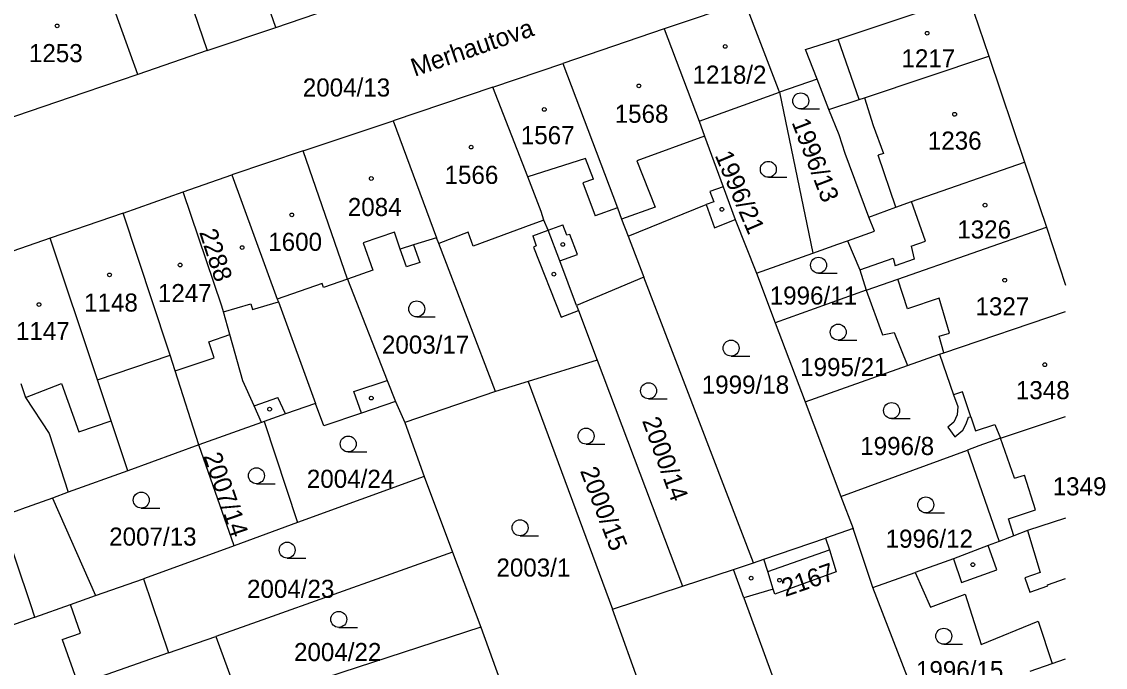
# Model space of a CAD drawing. Extents: x -564952 to -564307, y -1202373 to -1201847.
# Drawn here: x -564412.8 to -564310.9, y -1202215.7 to -1202155 of the extents above; entities that cross this region are included whole.
import ezdxf

# ---------------------------------------------------------------- set-up
doc = ezdxf.new("R2010")
doc.units = 0
for name, color, linetype in [('Hranice parcel', 7, 'Continuous'), ('Parcelní čísla', 7, 'Continuous'), ('Pop  PČ popisy', 7, 'Continuous'), ('Vnitřní kresba', 7, 'Continuous'), ('Značky budov', 7, 'Continuous'), ('Značky kultur', 7, 'Continuous')]:
    doc.layers.add(name, color=color, linetype=linetype)

msp = doc.modelspace()

# ---------------------------------------------------------------- linework, layer by layer
at = {"layer": 'Hranice parcel'}
for p, q in [((-564323.81, -1202152.55), (-564321.87, -1202158.24)), ((-564388.94, -1202155.54), (-564382.59, -1202153.39)), ((-564344.81, -1202153.14), (-564352.41, -1202155.68)), ((-564395.37, -1202157.69), (-564388.94, -1202155.54)), ((-564352.41, -1202155.68), (-564361.94, -1202158.92)), ((-564352.41, -1202155.68), (-564349.13, -1202164.34)), ((-564395.37, -1202157.69), (-564401.92, -1202159.96)), ((-564368.52, -1202161.14), (-564361.94, -1202158.92)), ((-564321.87, -1202158.24), (-564318.53, -1202168.2)), ((-564338.02, -1202160.39), (-564341.55, -1202161.62)), ((-564336.91, -1202163.24), (-564338.02, -1202160.39)), ((-564368.52, -1202161.14), (-564377.89, -1202164.3)), ((-564349.13, -1202164.34), (-564341.55, -1202161.62)), ((-564341.55, -1202161.62), (-564338.44, -1202176.75)), ((-564386.36, -1202167.12), (-564377.89, -1202164.3)), ((-564377.89, -1202164.3), (-564373.81, -1202175.3)), ((-564386.36, -1202167.12), (-564393.08, -1202169.4)), ((-564382.19, -1202179.19), (-564386.36, -1202167.12)), ((-564318.53, -1202168.2), (-564316.45, -1202174.31)), ((-564397.64, -1202171), (-564393.08, -1202169.4)), ((-564393.08, -1202169.4), (-564388.79, -1202181.06)), ((-564403.3, -1202172.98), (-564397.64, -1202171)), ((-564394.02, -1202181.72), (-564397.64, -1202171)), ((-564403.3, -1202172.98), (-564410.14, -1202175.34)), ((-564399.08, -1202185.67), (-564403.3, -1202172.98)), ((-564356.41, -1202173.55), (-564355.8, -1202175.14)), ((-564345.72, -1202173.6), (-564343.72, -1202178.62)), ((-564373.81, -1202175.3), (-564375.97, -1202175.98)), ((-564355.8, -1202175.14), (-564354.32, -1202179)), ((-564316.45, -1202174.31), (-564314.65, -1202179.77)), ((-564410.14, -1202175.34), (-564416.78, -1202177.62)), ((-564405.82, -1202188.28), (-564410.14, -1202175.34)), ((-564343.72, -1202178.62), (-564338.44, -1202176.75)), ((-564354.32, -1202179), (-564360.64, -1202181.66)), ((-564344.02, -1202205.84), (-564354.32, -1202179)), ((-564343.72, -1202178.62), (-564341.96, -1202183.28)), ((-564333.4, -1202180.24), (-564341.96, -1202183.28)), ((-564360.64, -1202181.66), (-564360.46, -1202182.13)), ((-564360.46, -1202182.13), (-564358.7, -1202186.81)), ((-564341.96, -1202183.28), (-564339.15, -1202190.71)), ((-564329.51, -1202187.3), (-564326.5, -1202186.24)), ((-564358.7, -1202186.81), (-564365.21, -1202188.81)), ((-564358.7, -1202186.81), (-564350.69, -1202208.05)), ((-564339.15, -1202190.71), (-564329.51, -1202187.3)), ((-564365.21, -1202188.81), (-564368.26, -1202189.75)), ((-564365.21, -1202188.81), (-564357.27, -1202210.21)), ((-564368.26, -1202189.75), (-564376.79, -1202192.67)), ((-564377.68, -1202190.7), (-564376.79, -1202192.67)), ((-564339.15, -1202190.71), (-564335.78, -1202199.6)), ((-564390.04, -1202192.58), (-564390.26, -1202192.66)), ((-564390.04, -1202192.58), (-564386.9, -1202202.07)), ((-564320.77, -1202194.12), (-564314.65, -1202192.1)), ((-564390.26, -1202192.66), (-564396.16, -1202194.76)), ((-564376.79, -1202192.67), (-564374.99, -1202197.73)), ((-564396.16, -1202194.76), (-564402.85, -1202197.21)), ((-564392.84, -1202204.24), (-564396.16, -1202194.76)), ((-564335.78, -1202199.6), (-564323.89, -1202195.26)), ((-564323.89, -1202195.26), (-564320.89, -1202203.83)), ((-564402.85, -1202197.21), (-564408.45, -1202199.22)), ((-564374.99, -1202197.73), (-564386.9, -1202202.07)), ((-564374.99, -1202197.73), (-564372.31, -1202204.85)), ((-564408.45, -1202199.22), (-564409.94, -1202199.76)), ((-564409.94, -1202199.76), (-564405.89, -1202208.93)), ((-564335.78, -1202199.6), (-564334.63, -1202202.63)), ((-564386.9, -1202202.07), (-564392.84, -1202204.24)), ((-564334.63, -1202202.63), (-564337.22, -1202203.52)), ((-564332.79, -1202208.17), (-564334.63, -1202202.63)), ((-564392.84, -1202204.24), (-564399.57, -1202206.7)), ((-564372.31, -1202204.85), (-564389.72, -1202211.06)), ((-564372.31, -1202204.85), (-564369.66, -1202211.88)), ((-564345.9, -1202206.48), (-564344.02, -1202205.84)), ((-564399.57, -1202206.7), (-564401.36, -1202207.34)), ((-564350.69, -1202208.05), (-564345.9, -1202206.48)), ((-564344.92, -1202209.13), (-564345.9, -1202206.48)), ((-564332.79, -1202208.17), (-564328.8, -1202206.76)), ((-564405.89, -1202208.93), (-564401.36, -1202207.34)), ((-564401.36, -1202207.34), (-564399.02, -1202214.32)), ((-564357.27, -1202210.21), (-564350.69, -1202208.05)), ((-564328.35, -1202219.63), (-564332.79, -1202208.17)), ((-564344.92, -1202209.13), (-564336.29, -1202232.6)), ((-564422.31, -1202214.68), (-564411.73, -1202210.99)), ((-564353.94, -1202219.47), (-564357.27, -1202210.21)), ((-564389.72, -1202211.06), (-564394.57, -1202212.76)), ((-564369.66, -1202211.88), (-564387.14, -1202217.59)), ((-564369.66, -1202211.88), (-564367.06, -1202219.05)), ((-564399.02, -1202214.32), (-564394.57, -1202212.76)), ((-564317.98, -1202216.02), (-564315.93, -1202215.31))]:
    msp.add_line(p, q, dxfattribs=at)
for points in [[(-564388.94, -1202155.54), (-564393.3, -1202143.04), (-564394.75, -1202139.64)], [(-564401.59, -1202140.42), (-564400.42, -1202143.26), (-564399.87, -1202144.59), (-564399.66, -1202145.21), (-564395.37, -1202157.69)], [(-564401.92, -1202159.96), (-564405.48, -1202150.04), (-564406.41, -1202147.46), (-564406.78, -1202146.53), (-564407.49, -1202144.77)], [(-564338.02, -1202160.39), (-564339.1, -1202157.6), (-564336.63, -1202156.83), (-564336.05, -1202156.64), (-564323.81, -1202152.55)], [(-564341.55, -1202161.62), (-564341.65, -1202161.36), (-564344.81, -1202153.14)], [(-564361.94, -1202158.92), (-564356.81, -1202172.49), (-564356.41, -1202173.55)], [(-564336.91, -1202163.24), (-564334.08, -1202162.32), (-564333.57, -1202162.15), (-564321.87, -1202158.24)], [(-564401.92, -1202159.96), (-564406.89, -1202161.65), (-564413.42, -1202163.87), (-564415.88, -1202164.71)], [(-564363.96, -1202172.83), (-564365.23, -1202169.56), (-564368.52, -1202161.14)], [(-564333.16, -1202173.36), (-564335.37, -1202167.37), (-564335.96, -1202165.63), (-564336.91, -1202163.24)], [(-564349.13, -1202164.34), (-564348.6, -1202165.74), (-564346.85, -1202170.52), (-564345.72, -1202173.6)], [(-564333.16, -1202173.36), (-564330.62, -1202172.43), (-564329.15, -1202171.9), (-564318.53, -1202168.2)], [(-564355.8, -1202175.14), (-564348.45, -1202172.16), (-564347.66, -1202174.38), (-564345.72, -1202173.6)], [(-564363.33, -1202174.6), (-564363.73, -1202173.64), (-564363.96, -1202172.83)], [(-564335.15, -1202175.59), (-564332.61, -1202174.69), (-564333.16, -1202173.36)], [(-564377.22, -1202176.37), (-564377.78, -1202174.76), (-564380.72, -1202175.77), (-564379.79, -1202178.36), (-564382.19, -1202179.19)], [(-564368.26, -1202189.75), (-564373.6, -1202175.84), (-564373.81, -1202175.3)], [(-564360.64, -1202181.66), (-564362.23, -1202177.48), (-564363.33, -1202174.6)], [(-564333.4, -1202180.24), (-564330.43, -1202179.2), (-564316.45, -1202174.31)], [(-564375.97, -1202175.98), (-564375.4, -1202177.63), (-564376.65, -1202178.02), (-564377.22, -1202176.37)], [(-564338.44, -1202176.75), (-564336.07, -1202175.91), (-564335.15, -1202175.59)], [(-564335.15, -1202175.59), (-564334.02, -1202178.32), (-564333.4, -1202180.24)], [(-564382.19, -1202179.19), (-564378.46, -1202188.71), (-564377.68, -1202190.7)], [(-564333.4, -1202180.24), (-564331.88, -1202184.42), (-564330.78, -1202184.21), (-564329.51, -1202187.3)], [(-564388.79, -1202181.06), (-564388.69, -1202181.33), (-564385.19, -1202190.86)], [(-564390.26, -1202192.66), (-564390.96, -1202191.11), (-564392.02, -1202188.74), (-564393.25, -1202184.4), (-564393.86, -1202182.27), (-564394.02, -1202181.72)], [(-564326.5, -1202186.24), (-564326.12, -1202186.1), (-564314.65, -1202182.22)], [(-564396.16, -1202194.76), (-564398.39, -1202187.82), (-564398.87, -1202186.32), (-564399.08, -1202185.67)], [(-564326.5, -1202186.24), (-564325.21, -1202190.06), (-564324.8, -1202191.17), (-564324.84, -1202191.95), (-564325.15, -1202192.62), (-564325.72, -1202193.11), (-564325.08, -1202194), (-564324.33, -1202193.39), (-564323.99, -1202192.78), (-564323.79, -1202192.16), (-564323.58, -1202192.12), (-564323.12, -1202193.45), (-564321.32, -1202192.84), (-564320.77, -1202194.12)], [(-564402.85, -1202197.21), (-564404.41, -1202192.51), (-564405.7, -1202188.65), (-564405.82, -1202188.28)], [(-564412.92, -1202189.01), (-564412.48, -1202190.3), (-564410.26, -1202193.68), (-564408.45, -1202199.22)], [(-564385.19, -1202190.86), (-564388.02, -1202191.86), (-564390.04, -1202192.58)], [(-564377.68, -1202190.7), (-564380.86, -1202191.77), (-564384.41, -1202192.97), (-564385.19, -1202190.86)], [(-564320.77, -1202194.12), (-564322.8, -1202194.86), (-564323.89, -1202195.26)], [(-564409.94, -1202199.76), (-564412.86, -1202200.81), (-564413, -1202200.86), (-564414.77, -1202201.48), (-564425.49, -1202205.25)], [(-564314.65, -1202201.64), (-564318.24, -1202202.82), (-564319.52, -1202203.31), (-564320.89, -1202203.83)], [(-564337.22, -1202203.52), (-564336.87, -1202204.62), (-564336.23, -1202206.68), (-564342, -1202208.78), (-564342.14, -1202208.33), (-564344.92, -1202209.13)], [(-564344.02, -1202205.84), (-564343.03, -1202205.5), (-564337.22, -1202203.52)], [(-564320.89, -1202203.83), (-564321.93, -1202204.23), (-564325.19, -1202205.48), (-564328.8, -1202206.76)], [(-564328.8, -1202206.76), (-564327.36, -1202210.02), (-564324.11, -1202208.79), (-564322.6, -1202213.51), (-564317.24, -1202211.33), (-564315.93, -1202215.31)], [(-564411.73, -1202210.99), (-564411.58, -1202210.94), (-564408.24, -1202209.76), (-564405.89, -1202208.93)], [(-564394.57, -1202212.76), (-564393.05, -1202216.87), (-564392.13, -1202219.38)], [(-564399.02, -1202214.32), (-564407.15, -1202217.16), (-564407.53, -1202217.29), (-564419.91, -1202221.63)], [(-564315.93, -1202215.31), (-564314.65, -1202214.86)]]:
    msp.add_lwpolyline(points, dxfattribs=at)
at = {"layer": 'Vnitřní kresba'}
for p, q in [((-564334.08, -1202162.32), (-564336.05, -1202156.64)), ((-564333.57, -1202162.15), (-564332.75, -1202164.74)), ((-564332.75, -1202164.74), (-564331.79, -1202167.37)), ((-564348.6, -1202165.74), (-564354.98, -1202168.08)), ((-564359.81, -1202167.84), (-564365.23, -1202169.56)), ((-564359.06, -1202169.79), (-564359.81, -1202167.84)), ((-564354.98, -1202168.08), (-564353.25, -1202172.43)), ((-564331.79, -1202167.37), (-564332.27, -1202167.55)), ((-564330.62, -1202172.43), (-564332.27, -1202167.55)), ((-564359.06, -1202169.79), (-564360.07, -1202170.15)), ((-564360.07, -1202170.15), (-564358.88, -1202173.23)), ((-564346.85, -1202170.52), (-564348.1, -1202170.95)), ((-564348.1, -1202170.95), (-564347.74, -1202171.92)), ((-564347.74, -1202171.92), (-564348.45, -1202172.16)), ((-564327.84, -1202175.61), (-564329.15, -1202171.9)), ((-564356.81, -1202172.49), (-564358.88, -1202173.23)), ((-564353.25, -1202172.43), (-564356.41, -1202173.55)), ((-564364.86, -1202174.06), (-564370.36, -1202176.1)), ((-564363.73, -1202173.64), (-564364.86, -1202174.06)), ((-564363.33, -1202174.6), (-564361.94, -1202174.1)), ((-564361.56, -1202175.07), (-564361.94, -1202174.1)), ((-564370.85, -1202174.78), (-564373.6, -1202175.84)), ((-564370.36, -1202176.1), (-564370.85, -1202174.78)), ((-564364.76, -1202175.12), (-564363.33, -1202174.6)), ((-564364.76, -1202175.12), (-564364.43, -1202176.05)), ((-564361.28, -1202175), (-564361.56, -1202175.07)), ((-564360.56, -1202176.87), (-564361.28, -1202175)), ((-564375.97, -1202175.98), (-564377.22, -1202176.37)), ((-564364.43, -1202176.05), (-564364.69, -1202176.19)), ((-564364.69, -1202176.19), (-564362.1, -1202182.77)), ((-564329.18, -1202176.09), (-564327.84, -1202175.61)), ((-564329.18, -1202176.09), (-564328.9, -1202177.32)), ((-564362.23, -1202177.48), (-564360.56, -1202176.87)), ((-564334.02, -1202178.32), (-564330.87, -1202177.21)), ((-564330.87, -1202177.21), (-564330.67, -1202177.95)), ((-564328.9, -1202177.32), (-564330.67, -1202177.95)), ((-564382.19, -1202179.19), (-564384.44, -1202179.99)), ((-564329.52, -1202181.98), (-564330.43, -1202179.2)), ((-564384.57, -1202179.61), (-564388.79, -1202181.06)), ((-564384.44, -1202179.99), (-564384.57, -1202179.61)), ((-564391.13, -1202182.04), (-564388.69, -1202181.33)), ((-564326.55, -1202180.97), (-564329.52, -1202181.98)), ((-564325.58, -1202184.26), (-564326.55, -1202180.97)), ((-564393.86, -1202182.27), (-564391.28, -1202181.52)), ((-564391.28, -1202181.52), (-564391.13, -1202182.04)), ((-564362.1, -1202182.77), (-564360.46, -1202182.13)), ((-564395.23, -1202185.07), (-564393.25, -1202184.4)), ((-564326.55, -1202184.56), (-564325.58, -1202184.26)), ((-564394.74, -1202186.58), (-564395.23, -1202185.07)), ((-564326.12, -1202186.1), (-564326.55, -1202184.56)), ((-564405.7, -1202188.65), (-564398.87, -1202186.32)), ((-564398.39, -1202187.82), (-564394.74, -1202186.58)), ((-564412.48, -1202190.3), (-564409.08, -1202189)), ((-564409.08, -1202189), (-564407.47, -1202193.55)), ((-564381.6, -1202189.76), (-564378.46, -1202188.71)), ((-564390.96, -1202191.11), (-564388.74, -1202190.32)), ((-564388.02, -1202191.86), (-564388.74, -1202190.32)), ((-564380.86, -1202191.77), (-564381.6, -1202189.76)), ((-564324.35, -1202189.77), (-564325.21, -1202190.06)), ((-564323.58, -1202192.12), (-564324.35, -1202189.77)), ((-564407.47, -1202193.55), (-564404.41, -1202192.51)), ((-564319.47, -1202197.88), (-564320.77, -1202194.12)), ((-564319.47, -1202197.88), (-564318.51, -1202197.62)), ((-564317.49, -1202200.86), (-564318.51, -1202197.62)), ((-564411.97, -1202209.79), (-564414.77, -1202201.48)), ((-564320.03, -1202201.7), (-564317.49, -1202200.86)), ((-564319.52, -1202203.31), (-564320.03, -1202201.7)), ((-564318.24, -1202202.82), (-564317.04, -1202206.75)), ((-564342.66, -1202206.67), (-564336.87, -1202204.62)), ((-564321.12, -1202206.5), (-564321.93, -1202204.23)), ((-564342.66, -1202206.67), (-564343.03, -1202205.5)), ((-564325.19, -1202205.48), (-564324.43, -1202207.69)), ((-564342.14, -1202208.33), (-564342.66, -1202206.67)), ((-564324.43, -1202207.69), (-564321.12, -1202206.5)), ((-564317.04, -1202206.75), (-564318.48, -1202207.25)), ((-564318.48, -1202207.25), (-564318.03, -1202208.59)), ((-564316.36, -1202207.92), (-564314.65, -1202207.32)), ((-564316.34, -1202208), (-564316.36, -1202207.92)), ((-564318.03, -1202208.59), (-564316.34, -1202208)), ((-564411.58, -1202210.94), (-564411.97, -1202209.79)), ((-564407.29, -1202212.45), (-564408.24, -1202209.76)), ((-564409.02, -1202213.06), (-564407.29, -1202212.45)), ((-564409.02, -1202213.06), (-564407.53, -1202217.29))]:
    msp.add_line(p, q, dxfattribs=at)
at = {"layer": 'Značky budov'}
for centre in [(-564409.5, -1202155.39), (-564327.68, -1202156.08), (-564346.66, -1202157.32), (-564354.78, -1202161.03), (-564363.68, -1202163.24), (-564325.09, -1202163.7), (-564370.56, -1202166.78), (-564379.95, -1202169.73), (-564322.23, -1202172.24), (-564387.43, -1202173.15), (-564346.98, -1202172.63), (-564392.1, -1202176.22), (-564361.94, -1202175.93), (-564397.93, -1202177.86), (-564404.57, -1202178.79), (-564362.78, -1202178.72), (-564320.38, -1202179.29), (-564411.2, -1202181.58), (-564316.61, -1202187.23), (-564379.95, -1202190.37), (-564389.51, -1202191.41), (-564323.38, -1202206.02), (-564344.23, -1202207.29), (-564341.55, -1202207.48)]:
    msp.add_circle(centre, 0.175, dxfattribs=at)
at = {"layer": 'Značky kultur'}
for p, q in [((-564339.56, -1202163.19), (-564337.81, -1202163.19)), ((-564342.61, -1202169.62), (-564340.86, -1202169.62)), ((-564337.89, -1202178.63), (-564336.14, -1202178.63)), ((-564375.68, -1202182.74), (-564373.93, -1202182.74)), ((-564336.04, -1202184.92), (-564334.29, -1202184.92)), ((-564346.11, -1202186.42), (-564344.36, -1202186.42)), ((-564353.87, -1202190.43), (-564352.12, -1202190.43)), ((-564331.02, -1202192.29), (-564329.27, -1202192.29)), ((-564382.12, -1202195.43), (-564380.37, -1202195.43)), ((-564359.75, -1202194.69), (-564358, -1202194.69)), ((-564390.75, -1202198.41), (-564389, -1202198.41)), ((-564401.58, -1202200.7), (-564399.83, -1202200.7)), ((-564327.8, -1202201.15), (-564326.05, -1202201.15)), ((-564365.96, -1202203.3), (-564364.21, -1202203.3)), ((-564387.86, -1202205.4), (-564386.11, -1202205.4)), ((-564383.01, -1202211.91), (-564381.26, -1202211.91)), ((-564326.11, -1202213.49), (-564324.36, -1202213.49))]:
    msp.add_line(p, q, dxfattribs=at)
for centre in [(-564339.56, -1202162.44), (-564342.61, -1202168.87), (-564337.89, -1202177.88), (-564375.68, -1202181.99), (-564336.04, -1202184.17), (-564346.11, -1202185.67), (-564353.87, -1202189.68), (-564331.02, -1202191.54), (-564359.75, -1202193.94), (-564382.12, -1202194.68), (-564390.75, -1202197.66), (-564401.58, -1202199.95), (-564327.8, -1202200.4), (-564365.96, -1202202.55), (-564387.86, -1202204.65), (-564383.01, -1202211.16), (-564326.11, -1202212.74)]:
    msp.add_circle(centre, 0.75, dxfattribs=at)

# ---------------------------------------------------------------- texts
at = {"layer": 'Parcelní čísla'}
for s, p in [('1253', (-564412.15, -1202158.8)), ('1217', (-564330.09, -1202159.29)), ('1218/2', (-564349.74, -1202160.82)), ('2004/13', (-564386.39, -1202162.03)), ('1568', (-564357.06, -1202164.5)), ('1567', (-564365.89, -1202166.51)), ('1236', (-564327.61, -1202167.02)), ('1566', (-564373.06, -1202170.24)), ('2084', (-564382.16, -1202173.26)), ('1326', (-564324.84, -1202175.37)), ('1600', (-564389.64, -1202176.53)), ('1247', (-564400.02, -1202181.35)), ('1996/11', (-564342.48, -1202181.58)), ('1148', (-564406.96, -1202182.24)), ('1327', (-564323.13, -1202182.6)), ('1147', (-564413.37, -1202184.92)), ('2003/17', (-564378.95, -1202186.19)), ('1995/21', (-564339.62, -1202188.3)), ('1999/18', (-564348.87, -1202189.95)), ('1348', (-564319.33, -1202190.47)), ('1996/8', (-564333.97, -1202195.72)), ('2004/24', (-564386.01, -1202198.8)), ('1349', (-564315.87, -1202199.51)), ('2007/13', (-564404.6, -1202204.23)), ('1996/12', (-564331.58, -1202204.43)), ('2003/1', (-564368.18, -1202207.14)), ('2004/23', (-564391.64, -1202209.14)), ('2004/22', (-564387.22, -1202215.08)), ('1996/15', (-564328.73, -1202216.78))]:
    msp.add_text(s, height=1.7, dxfattribs=at).set_placement(p)
for s, rotation, p in [('1996/13', 291, (-564340.44, -1202164.45)), ('1996/21', 293, (-564347.67, -1202167.55)), ('2288', 288, (-564396.15, -1202174.77)), ('2000/14', 290, (-564354.5, -1202192.49)), ('2007/14', 289, (-564395.75, -1202195.8)), ('2000/15', 291, (-564360.34, -1202197.2)), ('2167', 19, (-564341.01, -1202209.06))]:
    msp.add_text(s, height=1.7, rotation=rotation, dxfattribs=at).set_placement(p)
at = {"layer": 'Pop  PČ popisy'}
msp.add_text('Merhautova', height=1.7, rotation=19, dxfattribs=at).set_placement((-564375.87, -1202160.18))

doc.saveas('drawing.dxf')
